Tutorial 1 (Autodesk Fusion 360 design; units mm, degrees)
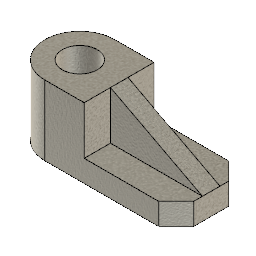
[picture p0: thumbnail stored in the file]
sketch "Sketch1" plane through (0, 0, 0) normal (0, 0, 1) x axis (1, 0, 0)
  line L1 (60, 16) -> (0, 16)
  line L2 (60, -16) -> (60, 16)
  line L3 (0, -16) -> (60, -16)
  arc A1 centre (0, 0) radius 16 clockwise from (0, -16) to (0, 16)
  point P1 (0, 0)
  point P2 (0, 0)
  coincident P1 P2
  tangent L1 A1
  horizontal L1
  perpendicular L1 L2
  tangent L3 A1
  horizontal L3
  dimension "d1" radius A1 = 16
  dimension "d2" distance P2 L2 = 60
extrude "Extrude1" new body sketch "Sketch1" along normal blind 10
sketch "Sketch2" plane through (0, 0, 10) normal (0, 0, 1) x axis (-1, 0, 0)
  line L1 (0, -16) -> (-60, -16)
  line L2 (-60, 16) -> (0, 16)
  line L3 (-60, -16) -> (-60, 16)
  line L4 (-18, 16) -> (-18, -16)
  line L5 (-18, 16) -> (0, 16)
  line L6 (-18, -16) -> (0, -16)
  arc A1 centre (0, 0) radius 16 clockwise from (0, 16) to (0, -16)
  arc A2 centre (0, 0) radius 16 clockwise from (0, 16) to (0, -16)
  point P1 (0, 0)
  point P7 (0, 0)
  point P8 (-18, -16)
  point P9 (-18, 16)
  point P4 (0, 16)
  point P10 (0, 16)
  point P3 (0, -16)
  point P11 (0, -16)
  coincident P1 P7
  coincident L1 P8
  coincident L2 P9
  perpendicular L2 L4
  coincident P4 P10
  tangent L5 A2
  coincident P3 P11
  tangent L6 A2
  dimension "d5" distance P7 L4 = 18
extrude "Extrude2" add sketch "Sketch2" profile of L1 A1 L2 A2 L4 L5 L6 along normal blind 22
sketch "Sketch3" plane through (0, 0, 32) normal (0, 0, 1) x axis (-1, 0, 0)
  line L1 (0, -16) -> (-18, -16)
  line L2 (-18, 16) -> (0, 16)
  line L3 (-18, -16) -> (-18, 16)
  arc A1 centre (0, 0) radius 16 clockwise from (0, 16) to (0, -16)
  circle C1 centre (0, 0) radius 8
  point P1 (0, 0)
  point P7 (0, 0)
  coincident P1 P7
  dimension "d8" diameter C1 = 16
extrude "Extrude3" cut sketch "Sketch3" profile of C1 no distance stored
sketch "Sketch6" plane through (0, 0, 0) normal (0, 1, 0) x axis (1, 0, 0)
  line L1 (60, -10) -> (18, -32)
  point P2 (18, -32)
  point P4 (18, -32)
  point P3 (60, -10)
  point P5 (60, -10)
  coincident P2 P4
  coincident P3 P5
step "Rib" Thickness 8
chamfer "Chamfer1" distance 8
